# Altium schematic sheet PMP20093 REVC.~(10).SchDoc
size 431 x 279 mm; Date: Not shown in title block; ApprovedBy: Not shown in title block; CheckedBy: Not shown in title block; Author: Not shown in title block; CompanyName: Not shown in title block; Engineer: Not shown in title block; Organization: Not shown in title block; Address1: Not shown in title block; Address2: Not shown in title block; Address3: Not shown in title block; Address4: Not shown in title block; DocumentNumber: 1; Revision: Use project parameter SCH_Rev; SheetNumber: 1; SheetTotal: 1; PageSetup: Record=PageOptions¦CenterHorizontal=True¦CenterVertical=True¦PrintScale=1.00¦XCorrection=1.00¦YCorrection=1.00¦PrintKind=0¦BorderSize=5000000¦LeftOffset=0¦BottomOffset=0¦Orientation=2¦PaperLength=1000¦PaperWidth=1000¦Scale=100¦PaperSource=15¦PrintQuality=600¦MediaType=1¦DitherType=10¦PaperKind=Letter¦PrintScaleMode=1
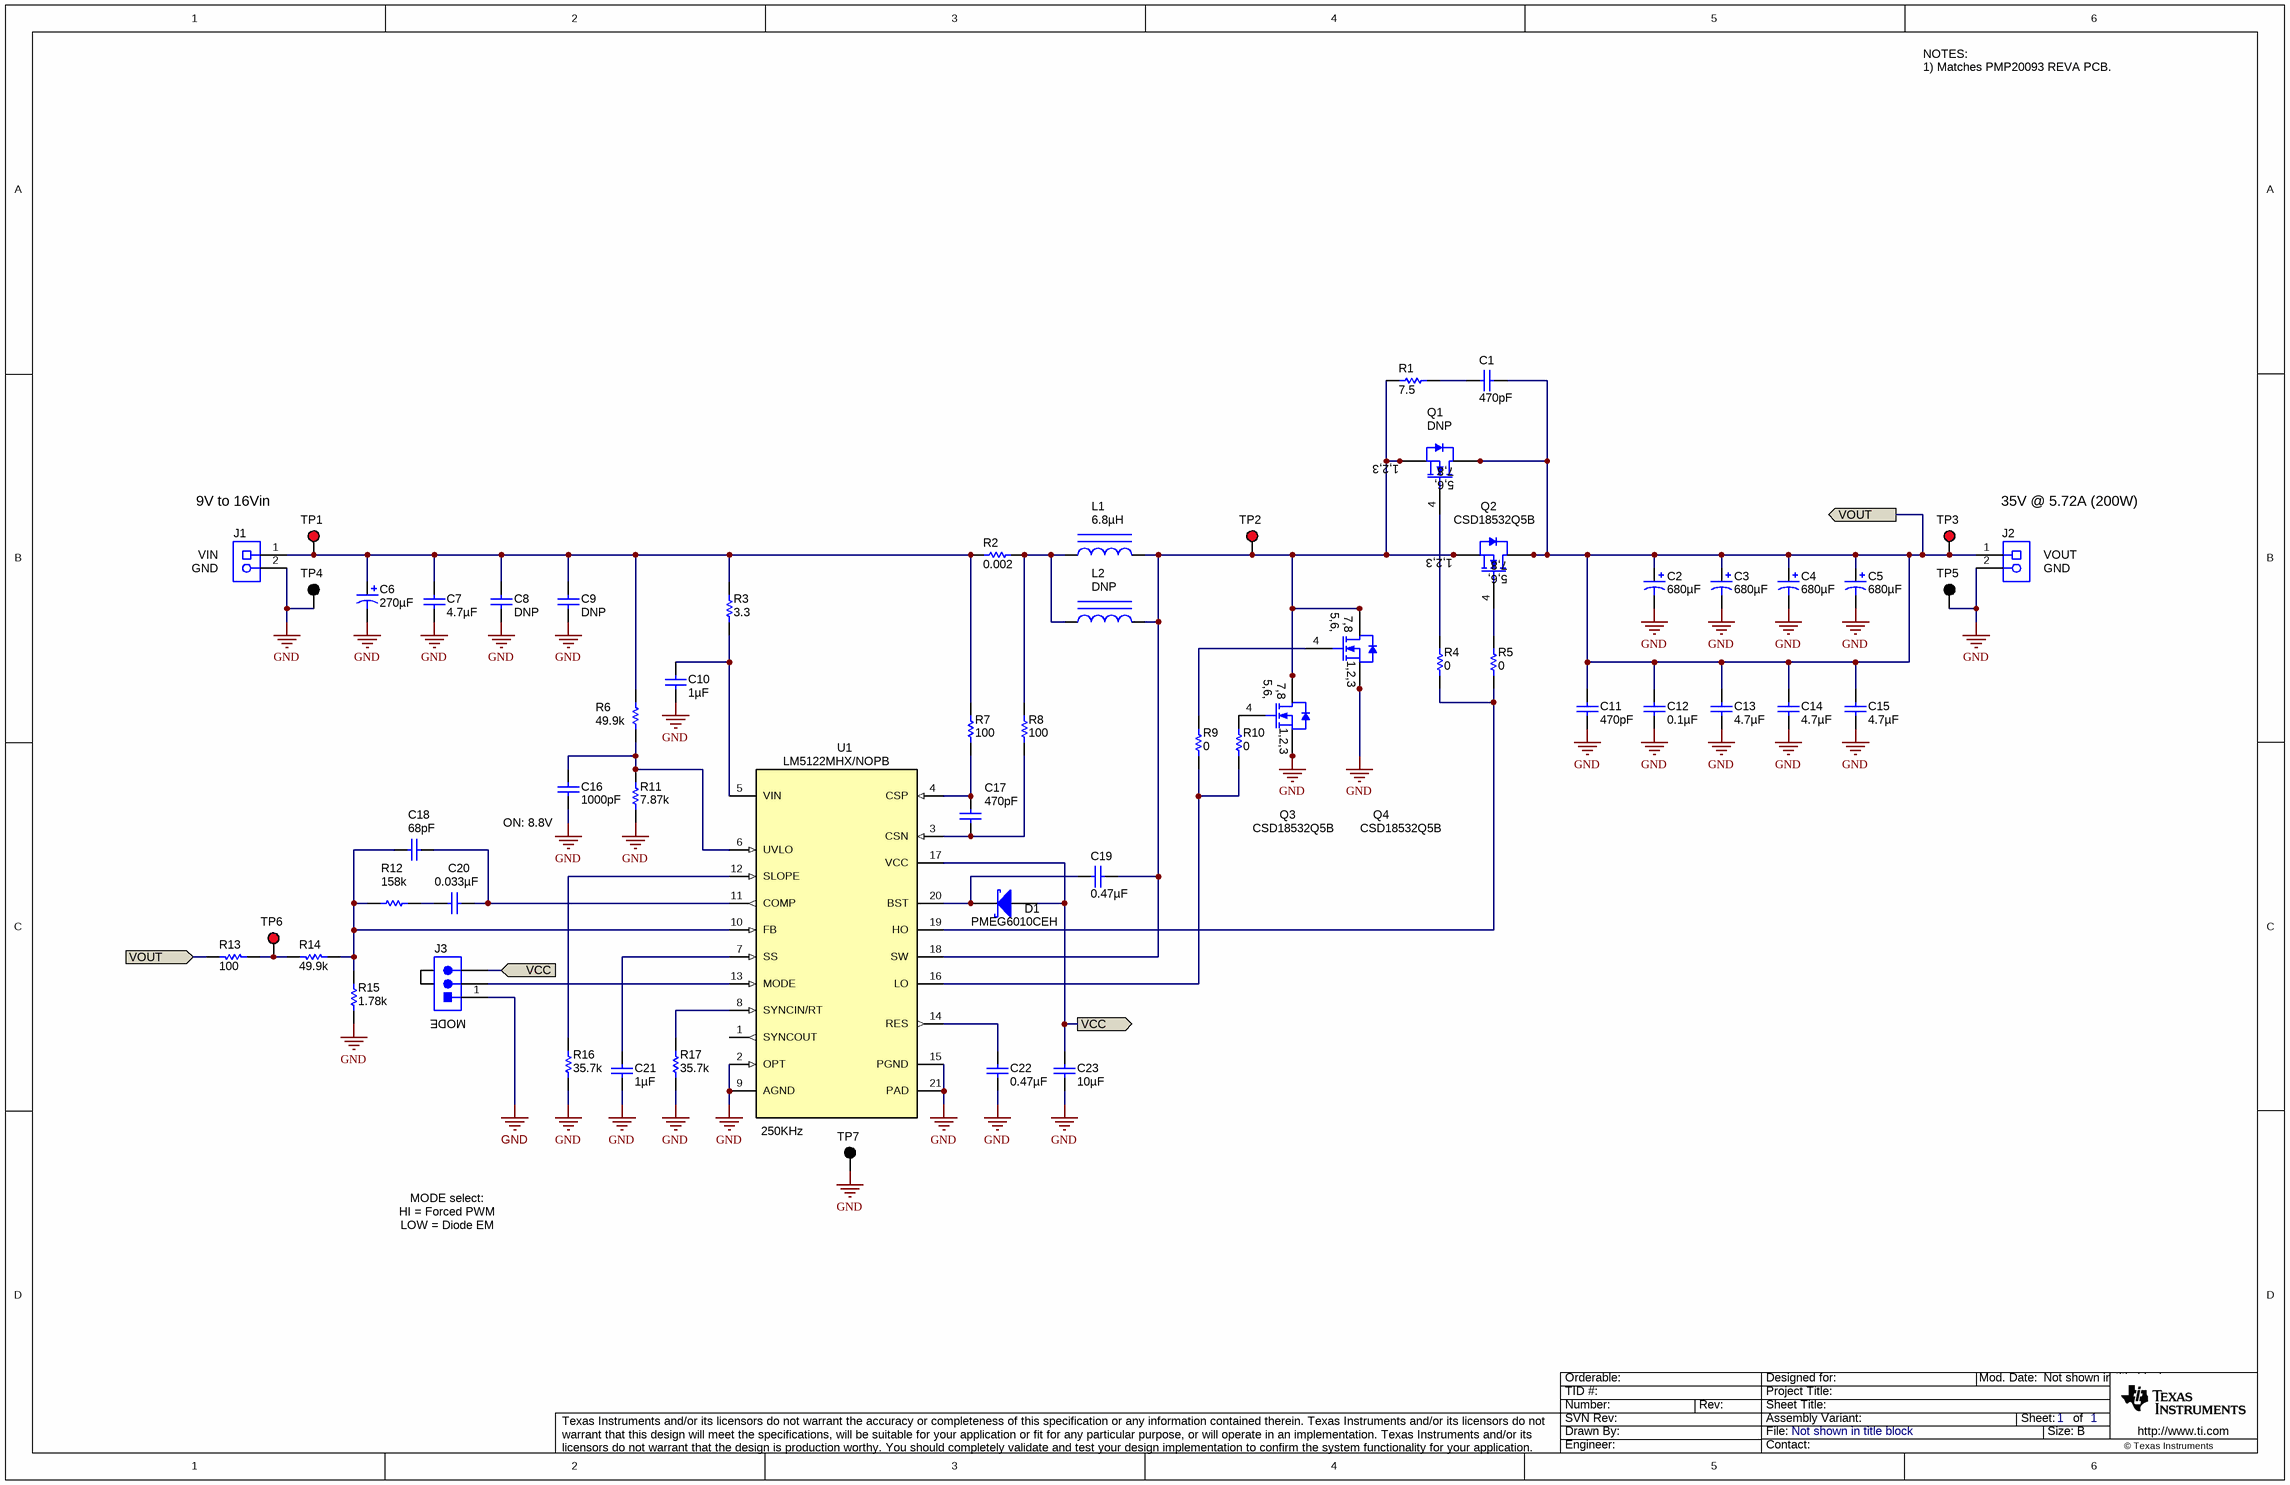
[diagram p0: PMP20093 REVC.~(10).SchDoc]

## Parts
C1  ValueDisplayed: 470pF  [0603]  (hidden comment: C1608C0G2A471J)
C2  ValueDisplayed: 680µF  [ZL_1250x2500]  (hidden comment: 50ZL680MEFC12.5X25)
C3  ValueDisplayed: 680µF  [ZL_1250x2500]  (hidden comment: 50ZL680MEFC12.5X25)
C4  ValueDisplayed: 680µF  [ZL_1250x2500]  (hidden comment: 50ZL680MEFC12.5X25)
C5  ValueDisplayed: 680µF  [ZL_1250x2500]  (hidden comment: 50ZL680MEFC12.5X25)
C6  ValueDisplayed: 270µF  [SM_RADIAL_10BMM]  (hidden comment: EEHZA1V271P)
C7  ValueDisplayed: 4.7µF  [1210_270]  (hidden comment: GRM32ER71H475KA88L)
C8  ValueDisplayed: DNP  [1210_270]
C9  ValueDisplayed: DNP  [1210_270]
C10  ValueDisplayed: 1µF  [0805_HV]  (hidden comment: C2012X7R1H105K125AB)
C11  ValueDisplayed: 470pF  [0603]  (hidden comment: C1608C0G2A471J)
C12  ValueDisplayed: 0.1µF  [0603]  (hidden comment: C1608X7R1H104K080AA)
C13  ValueDisplayed: 4.7µF  [1210_270]  (hidden comment: GRM32ER71H475KA88L)
C14  ValueDisplayed: 4.7µF  [1210_270]  (hidden comment: GRM32ER71H475KA88L)
C15  ValueDisplayed: 4.7µF  [1210_270]  (hidden comment: GRM32ER71H475KA88L)
C16  ValueDisplayed: 1000pF  [0603]  (hidden comment: GRM188R71H102KA01D)
C17  ValueDisplayed: 470pF  [0603]  (hidden comment: C1608C0G2A471J)
C18  ValueDisplayed: 68pF  [0603]  (hidden comment: GRM1885C1H680JA01D)
C19  ValueDisplayed: 0.47µF  [0603]  (hidden comment: GRM188R71E474KA12D)
C20  ValueDisplayed: 0.033µF  [0603]  (hidden comment: GRM188R71H333KA61D)
C21  ValueDisplayed: 1µF  [0603]  (hidden comment: C1608X7R1E105K080AB)
C22  ValueDisplayed: 0.47µF  [0603]  (hidden comment: GRM188R71E474KA12D)
C23  ValueDisplayed: 10µF  [0805_HV]  (hidden comment: GRM21BZ71E106KE15L)
D1  PMEG6010CEH  [SOD-123F]
J1  ED120/2DS  [On-Shore_ED120_2DS]  (value not drawn)
J2  ED120/2DS  [On-Shore_ED120_2DS]  (value not drawn)
J3  PEC03SAAN  [CONN_PEC03SAAN]  (value not drawn)
L1  ValueDisplayed: 6.8µH  [IHLP8787MZ]  (hidden comment: IHLP8787MZER6R8M5A)
L2  ValueDisplayed: DNP  [XAL1010]
Q1  value DNP  [DNK0008A]
Q2  CSD18532Q5B  [DNK0008A]
Q3  CSD18532Q5B  [DNK0008A]
Q4  CSD18532Q5B  [DNK0008A]
R1  ValueDisplayed: 7.5  [2010]  (hidden comment: CRM2010-JW-7R5ELF)
R2  ValueDisplayed: 0.002  [2512]  (hidden comment: CSNL2512FT2L00)
R3  value 3.3  [0603_HV]  (hidden comment: CRCW06033R30JNEA)
R4  ValueDisplayed: 0  [0603]  (hidden comment: CRCW06030000Z0EA)
R5  ValueDisplayed: 0  [0603]  (hidden comment: CRCW06030000Z0EA)
R6  value 49.9k  [0603]  (hidden comment: CRCW060349K9FKEA)
R7  ValueDisplayed: 100  [0603]  (hidden comment: CRCW0603100RFKEA)
R8  ValueDisplayed: 100  [0603]  (hidden comment: CRCW0603100RFKEA)
R9  ValueDisplayed: 0  [0603]  (hidden comment: CRCW06030000Z0EA)
R10  ValueDisplayed: 0  [0603]  (hidden comment: CRCW06030000Z0EA)
R11  ValueDisplayed: 7.87k  [0603]  (hidden comment: CRCW06037K87FKEA)
R12  ValueDisplayed: 158k  [0603]  (hidden comment: CRCW0603158KFKEA)
R13  value 100  [0603]  (hidden comment: CRCW0603100RFKEA)
R14  value 49.9k  [0603]  (hidden comment: CRCW060349K9FKEA)
R15  ValueDisplayed: 1.78k  [0603]  (hidden comment: CRCW06031K78FKEA)
R16  ValueDisplayed: 35.7k  [0603]  (hidden comment: CRCW060335K7FKEA)
R17  ValueDisplayed: 35.7k  [0603]  (hidden comment: CRCW060335K7FKEA)
TP1  5010  [Keystone5010]  (value not drawn)
TP2  5010  [Keystone5010]  (value not drawn)
TP3  5010  [Keystone5010]  (value not drawn)
TP4  5011  [Keystone5011]  (value not drawn)
TP5  5011  [Keystone5011]  (value not drawn)
TP6  5010  [Keystone5010]  (value not drawn)
TP7  5011  [Keystone5011]  (value not drawn)
U1  LM5122MHX/NOPB  [PWP0020A_N]

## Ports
VCC, VOUT

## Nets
GND: C2.2(-) C3.2(-) C4.2(-) C5.2(-) C6.2(-) C7.2 C8.2 C9.2 C10.1 C11.2 C12.1 C13.2 C14.2 C15.2 C16.2 C21.2 C22.1 C23.2 J1.2 J2.2 J3.1 Q3.1(S) Q3.2(S) Q3.3(S) Q4.1(S) Q4.2(S) Q4.3(S) R11.1 R15.1 R16.1 R17.1 TP4.1 TP5.1 TP7.1 U1.2(OPT) U1.9(AGND) U1.15(PGND) U1.21(PAD)
VCC: C23.1 D1.2(A) J3.3 U1.17(VCC) ; port VCC
VOUT: C1.1 C2.1(+) C3.1(+) C4.1(+) C5.1(+) C11.1 C12.2 C13.1 C14.1 C15.1 J2.1 Q1.5(D) Q1.6(D) Q1.7(D) Q1.8(D) Q1.9(D) Q2.5(D) Q2.6(D) Q2.7(D) Q2.8(D) Q2.9(D) R13.2 TP3.1 ; port VOUT
NetC1_2: C1.2 R1.2
NetC6_1: C6.1(+) C7.1 C8.1 C9.1 J1.1 R2.1 R3.2 R6.2 R7.1 TP1.1
NetC10_2: C10.2 R3.1 U1.5(VIN)
NetC16_1: C16.1 R6.1 R11.2 U1.6(UVLO)
NetC17_1: C17.1 R7.2 U1.4(CSP)
NetC17_2: C17.2 R8.2 U1.3(CSN)
NetC18_1: C18.1 C20.1 U1.11(COMP)
NetC18_2: C18.2 R12.1 R14.1 R15.2 U1.10(FB)
NetC19_1: C19.1 L1.2 L2.2 Q1.1(S) Q1.2(S) Q1.3(S) Q2.1(S) Q2.2(S) Q2.3(S) Q3.5(D) Q3.6(D) Q3.7(D) Q3.8(D) Q3.9(D) Q4.5(D) Q4.6(D) Q4.7(D) Q4.8(D) Q4.9(D) R1.1 TP2.1 U1.18(SW)
NetC19_2: C19.2 D1.1(K) U1.20(BST)
NetC20_2: C20.2 R12.2
NetC21_1: C21.1 U1.7(SS)
NetC22_2: C22.2 U1.14(RES)
NetJ3_2: J3.2 U1.13(MODE)
NetL1_1: L1.1 L2.1 R2.2 R8.1
NetQ1_4: Q1.4(G) R4.2
NetQ2_4: Q2.4(G) R5.2
NetQ3_4: Q3.4(G) R10.2
NetQ4_4: Q4.4(G) R9.1
NetR4_1: R4.1 R5.1 U1.19(HO)
NetR9_2: R9.2 R10.1 U1.16(LO)
NetR13_1: R13.1 R14.2 TP6.1
NetR16_2: R16.2 U1.12(SLOPE)
NetR17_2: R17.2 U1.8(SYNCIN/RT)

Not connected (* = marked no-connect by the designer): U1 1(SYNCOUT)

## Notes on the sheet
- NOTES:
  1) Matches PMP20093 REVA PCB.
- 9V to 16Vin
- 35V @ 5.72A (200W)
- (near J1) VIN
- (near J1) GND
- (near J2) VOUT
- (near J2) GND
- (near C16) ON: 8.8V
- (near J3) MODE
- 250KHz
- MODE select:
- HI = Forced PWM
- LOW = Diode EM

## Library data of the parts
C1 C11 C17 = C1608C0G2A471J: CAP, CERM, 470 pF, 100 V, +/- 5%, C0G/NP0, 0603; Manufacturer: TDK; Polarized: N; CompType: Capacitor; Value: 470pF; U/M: EA; Cap_F: 0.00000000047; Tolerance_%: 5; ESR_ohm: 0.0714; Value1: 0.0714 ohm; VDC_V: 100; Value2: 100V; TaMin_C: -55; TaMax_C: 125; SizeArea_mm2: 1.28; SizeAreaWB_mm2: 4.68; SizeX_mm: 1.6; SizeY_mm: 0.8; SizeZ_mm: 1; AEC Category: Q200
C2-C5 = 50ZL560MEFC12.5X25: CAP, AL, 680 µF, 50 V, +/- 20%, 2.86A, 0.021 ohm, TH; Manufacturer: Rubycon; Polarized: Y; CompType: Capacitor; Value: 680uF; U/M: EA; Cap_F: 0.00056; Tolerance_%: 20; VDC_V: 50; Value2: 50V; ESR_ohm: 0.023; IRMS_A: 2.41; TaMin_C: -40; TaMax_C: 105; Cap_Case: 12.5x25mm; AEC Category: Q200; AEC Qualified: N
C6 = EEHZA1V271P: CAP, Polymer Hybrid, 270 µF, 35 V, +/- 20%, 20 ohm, 10x10 SMD; Manufacturer: Panasonic; Polarized: Y; CompType: Capacitor; Value: 270uF; U/M: EA; Cap_F: 0.00027; Tolerance_%: 20; Value1: 20 ohm; VDC_V: 35; Value2: 35V; IRMS_A: 2.5; TaMin_C: -55; TaMax_C: 105; AEC Category: Q200
C7 C13-C15 = GRM32ER71H475KA88L: CAP, CERM, 4.7 µF, 50 V, +/- 10%, X7R, 1210; Manufacturer: MuRata; Polarized: N; CompType: Capacitor; Value: 4.7uF; U/M: EA; Cap_F: 0.0000047; Tolerance_%: 10; ESR_ohm: 0.002; Value1: 0.002 ohm; VDC_V: 50; Value2: 50V; TaMin_C: -55; TaMax_C: 125; Cap_Case: 1210; SizeArea_mm2: 8; SizeAreaWB_mm2: 14.7; SizeX_mm: 3.2; SizeY_mm: 2.5; SizeZ_mm: 2.7; AEC Category: Q200
C8 C9 = GRM32ER71H475KA88L: CAP, CERM, 1210; Polarized: N; CompType: Capacitor; U/M: EA; Tolerance_%: 10; ESR_ohm: 0.002; TaMin_C: -55; TaMax_C: 125; Cap_Case: 1210; SizeArea_mm2: 8; SizeAreaWB_mm2: 14.7; AEC Category: Q200
C10 = C2012X7R1H105K125AB: CAP, CERM, 1 µF, 50 V, +/- 10%, X7R, 0805; Manufacturer: TDK; Polarized: N; CompType: Capacitor; Value: 1uF; U/M: EA; Cap_F: 0.000001; Tolerance_%: 10; ESR_ohm: 0.008782; Value1: 0.008782 ohm; VDC_V: 50; Value2: 50V; IRMS_A: 2.20488; TaMin_C: -55; TaMax_C: 125; Cap_Case: 0805; SizeArea_mm2: 2.5; SizeAreaWB_mm2: 6.75; SizeX_mm: 2; SizeY_mm: 1.25; SizeZ_mm: 1.45; AEC Category: Q200
C12 = C1608X7R1H104K080AA: CAP, CERM, 0.1 µF, 50 V, +/- 10%, X7R, 0603; Manufacturer: TDK; Polarized: N; CompType: Capacitor; Value: 0.1uF; U/M: EA; Cap_F: 0.0000001; Tolerance_%: 10; ESR_ohm: 0.0296; Value1: 0.0296 ohm; VDC_V: 50; Value2: 50V; IRMS_A: 0.97199; TaMin_C: -55; TaMax_C: 125; AEC Category: Q200; SizeArea_mm2: 1.28; SizeAreaWB_mm2: 4.68; SizeX_mm: 1.6; SizeY_mm: 0.8; SizeZ_mm: 1
C16 = GRM188R71H102KA01D: CAP, CERM, 1000pF, 50V, +/-10%, X7R, 0603; Manufacturer: MuRata; Polarized: N; CompType: Capacitor; U/M: EA; Cap_F: 0.000000001; Tolerance_%: 10; Value1: Unknown; VDC_V: 50; TaMin_C: -55; TaMax_C: 125
C18 = GRM1885C1H680JA01D: CAP, CERM, 68 pF, 50 V, +/- 5%, C0G/NP0, 0603; Manufacturer: MuRata; Polarized: N; CompType: Capacitor; Value: 68pF; U/M: EA; Cap_F: 0.000000000068; Tolerance_%: 5; Value1: Unknown; VDC_V: 50; Value2: 50V; TaMin_C: -55; TaMax_C: 125; SizeArea_mm2: 1.28; SizeAreaWB_mm2: 4.68; SizeX_mm: 1.6; SizeY_mm: 0.8; SizeZ_mm: 1; AEC Category: Q200
C19 C22 = GRM188R71E474KA12D: CAP, CERM, 0.47uF, 25V, +/-10%, X7R, 0603; Manufacturer: MuRata; Polarized: N; CompType: Capacitor; U/M: EA; Cap_F: 0.00000047; Tolerance_%: 10; Value1: Unknown; VDC_V: 25; TaMin_C: -55; TaMax_C: 125
C20 = GRM188R71H333KA61D: CAP, CERM, 0.033 µF, 50 V, +/- 10%, X7R, 0603; Manufacturer: MuRata; Polarized: N; CompType: Capacitor; Value: 0.033uF; U/M: EA; Cap_F: 0.000000033; Tolerance_%: 10; Value1: Unknown; VDC_V: 50; Value2: 50V; TaMin_C: -55; TaMax_C: 125; SizeArea_mm2: 1.28; SizeAreaWB_mm2: 4.68; SizeX_mm: 1.6; SizeY_mm: 0.8; SizeZ_mm: 1; AEC Category: Q200
C21 = C1608X7R1E105K080AB: CAP, CERM, 1 µF, 25 V, +/- 10%, X7R, 0603; Manufacturer: TDK; Polarized: N; CompType: Capacitor; Value: 1uF; U/M: EA; Cap_F: 0.000001; Tolerance_%: 10; Value1: Unknown; VDC_V: 25; Value2: 25V; TaMin_C: -55; TaMax_C: 125; AEC Category: Q200
C23 = GRM21BZ71E106KE15L: CAP, CERM, 10 µF, 25 V, +/- 10%, X7R, 0805; Manufacturer: MuRata; Polarized: N; CompType: Capacitor; Value: 10uF; U/M: EA; Cap_F: 0.00001; Tolerance_%: 10; Value1: Unknown; VDC_V: 25; Value2: 25V; TaMin_C: -55; TaMax_C: 125; Cap_Case: 0805; SizeArea_mm2: 2.5; SizeAreaWB_mm2: 6.75; SizeX_mm: 2; SizeY_mm: 1.25; SizeZ_mm: 1.45; AEC Category: Q200
D1 = PMEG6010CEH,115: Diode, Schottky, 60V, 1A, SOD-123F; Manufacturer: NXP Semiconductor; U/M: EA; Vf_V: 0.57; Value2: 0.57V; Io_A: 1; Vr_V: 60; TJmax_C: 150
J1 J2 = ED120/2DS: Terminal Block, 5.08 mm, 2x1, Brass, TH; Manufacturer: On-Shore Technology; SymbolCreator: a0412235; Pitch_mm: 5.08; Gender: Female; Shrouded: N; Row_Count: 1; Current_A: 15; Voltage_V: 300; Cert_CULUS: Y
J3 = PEC03SAAN: Header, 100mil, 3x1, Tin, TH; Manufacturer: Sullins Connector Solutions; SymbolCreator: a0799628; Pitch_mm: 2.54; Gender: Male; Shrouded: N; Row_Count: 1; Current_A: 3; Voltage_V: 1800; Cert_UL: Y
L1 = IHLP8787MZER100M5A: Inductor, Shielded, 6.8 µH, 36A, 0.00284 ohm, AEC-Q200 Grade 0, SMD; Manufacturer: Vishay-Dale; Value: 6.8uH; AEC Category: Q200; AEC Qualified: Y; AEC Grade: 0
L2 = XAL1010-222MEB: Inductor, SMD, alternate footprint; U/M: EA
Q1 = CSD18532Q5B: MOSFET, N-CH, DNP; Alternate Manufacturer: None; U/M: EA; ChType: N; IdsMax_A: 172; SizeAreaWB_mm2: 56; SizeArea_mm2: 30; AEC Category: Q101
Q2-Q4 = CSD18532Q5B: MOSFET, N-CH, 60 V, 172 A, DNK0008A (VSON-CLIP-8); Manufacturer: Texas Instruments; Alternate Manufacturer: None; U/M: EA; ChType: N; Value: 60V; VdsMax_V: 60; Value1: 3.3 ohm; Rdson45_ohm: 3.3; Value2: 27 nC; QgTyp_nC: 27; Vgs_V: 1.6; IdsMax_A: 172; SizeAreaWB_mm2: 56; SizeArea_mm2: 30; SizeX_mm: 6; SizeY_mm: 5; SizeZ_mm: 1; AEC Category: Q101
R1 = CRM2010-JW-7R5ELF: RES, 7.5, 5%, 1 W, 2010; Manufacturer: Bourns; CompType: Resistor; Value: 7.5; Value_Code: 7R50; Tolerance_%: 5; Power_W: 1; Value2: 1W; VDC_V: 3; TempCo: 100 ppm/C; SizeArea_mm2: 12.5; SizeY_mm: 2.5; SizeZ_mm: 1.66; EIA_Code: E24; U/M: EA; AEC Category: Q200
R2 = CSNL2512FT2L00: RES, 0.002, 1%, 2 W, 2512; Manufacturer: Stackpole Electronics Inc; CompType: Resistor; Value: 0.002; Value_Code: 2L000; Tolerance_%: 1; Power_W: 2; Value2: 2W; VDC_V: 200; TempCo: 50 ppm/C; SizeArea_mm2: 20.16; SizeX_mm: 6.3; SizeY_mm: 3.2; SizeZ_mm: 0.71; U/M: EA; AEC Category: Q200
R3 = CRCW06033R30JNEA: RES, 3.3 ohm, 5%, 0.1W, 0603; Manufacturer: Vishay-Dale; CompType: Resistor; Value_Code: 3R30; Tolerance_%: 5; Power_W: 0.1; VDC_V: 75; TempCo: 200 ppm/C; EIA_Code: E24; U/M: EA
R4 R5 R9 R10 = CRCW06030000Z0EA: RES, 0, 5%, 0.1 W, 0603; Manufacturer: Vishay-Dale; CompType: Resistor; Value: 0; Value_Code: 0000; Tolerance_%: 5; Power_W: 0.1; Value2: 0.1W; VDC_V: 75; TempCo: 200 ppm/C; EIA_Code: E24; U/M: EA; SizeArea_mm2: 1.28; SizeX_mm: 1.6; SizeY_mm: 0.8; SizeZ_mm: 1; AEC Category: Q200
R6 R14 = CRCW060349K9FKEA: RES, 49.9k ohm, 1%, 0.1W, 0603; Manufacturer: Vishay-Dale; CompType: Resistor; Res_ohm: 49900; Value_Code: 49k9; Tolerance_%: 1; Power_W: 0.1; VDC_V: 75; TempCo: 100 ppm/C; EIA_Code: E96; U/M: EA
R7 R8 = CRCW0603100RFKEA: RES, 100, 1%, 0.1 W, 0603; Manufacturer: Vishay-Dale; CompType: Resistor; Value: 100; Value_Code: 100R; Tolerance_%: 1; Power_W: 0.1; Value2: 0.1W; VDC_V: 75; TempCo: 100 ppm/C; EIA_Code: E96; U/M: EA; SizeArea_mm2: 1.28; SizeX_mm: 1.6; SizeY_mm: 0.8; AEC Category: Q200
R11 = CRCW06037K87FKEA: RES, 7.87 k, 1%, 0.1 W, 0603; Manufacturer: Vishay-Dale; CompType: Resistor; Value: 7.87k; Res_ohm: 7870; Value_Code: 7k87; Tolerance_%: 1; Power_W: 0.1; Value2: 0.1W; VDC_V: 75; TempCo: 100 ppm/C; EIA_Code: E96; U/M: EA; AEC Category: Q200
R12 = CRCW0603158KFKEA: RES, 158 k, 1%, 0.1 W, 0603; Manufacturer: Vishay-Dale; CompType: Resistor; Value: 158k; Res_ohm: 158000; Tolerance_%: 1; Power_W: 0.1; Value2: 0.1W; VDC_V: 75; TempCo: 100 ppm/C; EIA_Code: E96; U/M: EA; AEC Category: Q200
R13 = CRCW0603100RFKEA: RES, 100 ohm, 1%, 0.1W, 0603; Manufacturer: Vishay-Dale; CompType: Resistor; Value_Code: 100R; Tolerance_%: 1; Power_W: 0.1; VDC_V: 75; TempCo: 100 ppm/C; EIA_Code: E96; U/M: EA
R15 = CRCW06031K78FKEA: RES, 1.78 k, 1%, 0.1 W, 0603; Manufacturer: Vishay-Dale; CompType: Resistor; Value: 1.78k; Res_ohm: 1780; Value_Code: 1k78; Tolerance_%: 1; Power_W: 0.1; Value2: 0.1W; VDC_V: 75; TempCo: 100 ppm/C; EIA_Code: E96; U/M: EA; AEC Category: Q200
R16 R17 = CRCW060335K7FKEA: RES, 35.7 k, 1%, 0.1 W, 0603; Manufacturer: Vishay-Dale; CompType: Resistor; Value: 35.7k; Res_ohm: 35700; Value_Code: 35k7; Tolerance_%: 1; Power_W: 0.1; Value2: 0.1W; VDC_V: 75; TempCo: 100 ppm/C; EIA_Code: E96; U/M: EA; AEC Category: Q200
TP1-TP3 TP6 = 5010: Test Point, Multipurpose, Red, TH; Manufacturer: Keystone; CompType: Test Point Loop; U/M: EA
TP4 TP5 TP7 = 5011: Test Point, Multipurpose, Black, TH; Manufacturer: Keystone; CompType: Test Point Loop; U/M: EA
U1 = LM5122MHX/NOPB: Wide Input Synchronous Boost Controller with Multiple Phase Capability, PWP0020A (TSSOP-20); Alternate PartNumber: LM5122MHE/NOPB; Manufacturer: Texas Instruments; SymbolCreator: a0411947; SizeArea_mm2: 41.6; SizeAreaWB_mm2: 71.4; SizeX_mm: 6.4; SizeY_mm: 6.5; SizeZ_mm: 1.2; CompType: IC; U/M: EA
